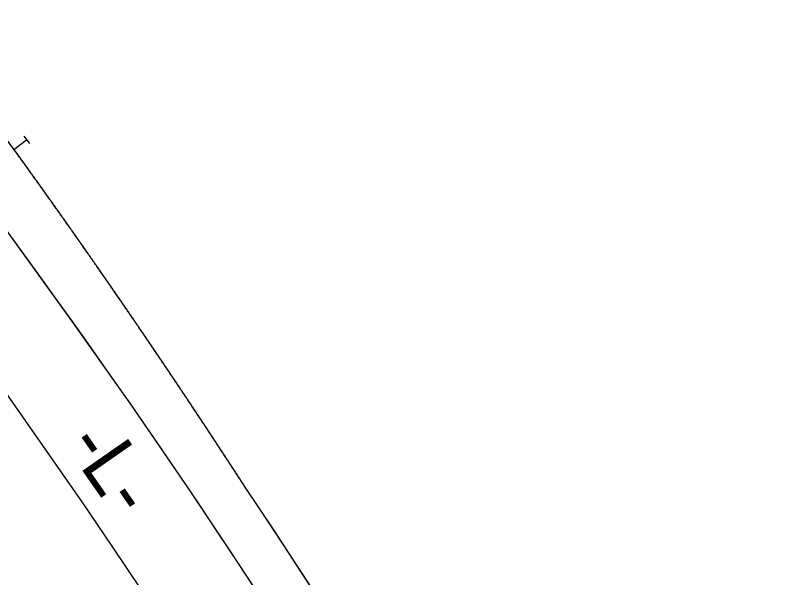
# Model space of a CAD drawing. Extents: x 2057680 to 2059216, y 687940 to 689338.
# Drawn here: x 2058908.2 to 2059006.1, y 688642.4 to 688713 of the extents above; entities that cross this region are included whole.
import ezdxf

# ---------------------------------------------------------------- set-up
doc = ezdxf.new("R2010")
doc.units = 0
for name, color, linetype in [('Cogo Default Point CELL', 7, 'Continuous'), ('COGO Default Point Elevation', 7, 'Continuous'), ('Exist DTM Breakline Cogo Number', 7, 'Continuous'), ('Exist DTM Breakline Cogo Point CELL', 7, 'Continuous'), ('Exist DTM Regular Point Underwater Cogo Number', 7, 'Continuous'), ('Exist Roads EOP Cogo Elevation', 7, 'Continuous'), ('Exist Structure Major Bridge WW Cogo Point CELL', 7, 'Continuous'), ('Exist Structure Major Deck Tunnel Box Culvert Cogo Elevation', 7, 'Continuous'), ('Exist Structure Major Deck Tunnel Box Culvert Cogo Number', 7, 'Continuous')]:
    doc.layers.add(name, color=color, linetype=linetype)

msp = doc.modelspace()

# ---------------------------------------------------------------- linework, layer by layer
at = {"layer": 'Cogo Default Point CELL'}
msp.add_arc((2058091.567, 688086.697), 1000, 13.858564, 62.505867, dxfattribs=at)
at = {"layer": 'Exist DTM Breakline Cogo Number'}
for p, q in [((2058907.962, 688696.191), (2058909.553, 688697.403)), ((2058909.206, 688697.859), (2058909.9, 688696.947))]:
    msp.add_line(p, q, dxfattribs=at)
at = {"layer": 'Exist DTM Breakline Cogo Point CELL'}
for radius, start, end in [(1018.818, 36.724192, 37.798292), (1018.01, 21.684059, 33.859403)]:
    msp.add_arc((2058091.567, 688086.697), radius, start, end, dxfattribs=at)
msp.add_spline([(2058936.93, 688653.889), (2058936.555, 688654.466), (2058936.181, 688655.043), (2058935.805, 688655.619), (2058935.43, 688656.196), (2058935.054, 688656.772), (2058934.678, 688657.348), (2058934.301, 688657.924), (2058933.924, 688658.499), (2058933.546, 688659.074), (2058933.168, 688659.649), (2058932.79, 688660.224), (2058932.411, 688660.798), (2058932.032, 688661.372), (2058931.653, 688661.946), (2058931.273, 688662.52), (2058930.893, 688663.093), (2058930.512, 688663.666), (2058930.131, 688664.239), (2058929.75, 688664.812), (2058929.368, 688665.384), (2058928.985, 688665.957), (2058928.603, 688666.529), (2058928.22, 688667.1), (2058927.837, 688667.672), (2058927.453, 688668.243), (2058927.069, 688668.814), (2058926.684, 688669.384), (2058926.299, 688669.955), (2058925.914, 688670.525), (2058925.528, 688671.095), (2058925.142, 688671.664), (2058924.755, 688672.234), (2058924.368, 688672.803), (2058923.981, 688673.372), (2058923.594, 688673.94), (2058923.205, 688674.509), (2058922.817, 688675.077), (2058922.428, 688675.645), (2058922.039, 688676.212), (2058921.649, 688676.779), (2058921.259, 688677.346), (2058920.869, 688677.913), (2058920.478, 688678.48), (2058920.087, 688679.046), (2058919.695, 688679.612), (2058919.304, 688680.178), (2058918.911, 688680.743), (2058918.519, 688681.309), (2058918.125, 688681.874), (2058917.732, 688682.438), (2058917.338, 688683.003), (2058916.944, 688683.567), (2058916.549, 688684.131), (2058916.154, 688684.695), (2058915.759, 688685.258), (2058915.363, 688685.821), (2058914.967, 688686.384), (2058914.57, 688686.947), (2058914.173, 688687.509), (2058913.776, 688688.071), (2058913.378, 688688.633), (2058912.98, 688689.195), (2058912.582, 688689.756), (2058912.183, 688690.317), (2058911.784, 688690.878), (2058911.384, 688691.439), (2058910.984, 688691.999), (2058910.584, 688692.559), (2058910.183, 688693.119), (2058909.782, 688693.678), (2058909.38, 688694.237), (2058908.978, 688694.796), (2058908.173, 688695.913)], degree=3, dxfattribs=at)
at = {"layer": 'Exist DTM Regular Point Underwater Cogo Number'}
msp.add_arc((2058091.567, 688086.697), 1018, 21.684059, 33.859412, dxfattribs=at)
msp.add_spline([(2058936.921, 688653.883), (2058936.547, 688654.46), (2058936.172, 688655.037), (2058935.797, 688655.614), (2058935.422, 688656.19), (2058935.046, 688656.766), (2058934.669, 688657.342), (2058934.293, 688657.918), (2058933.915, 688658.493), (2058933.538, 688659.069), (2058933.16, 688659.644), (2058932.782, 688660.218), (2058932.403, 688660.793), (2058932.024, 688661.367), (2058931.644, 688661.941), (2058931.265, 688662.514), (2058930.884, 688663.088), (2058930.504, 688663.661), (2058930.123, 688664.234), (2058929.741, 688664.806), (2058929.359, 688665.379), (2058928.977, 688665.951), (2058928.595, 688666.523), (2058928.212, 688667.095), (2058927.828, 688667.666), (2058927.444, 688668.237), (2058927.06, 688668.808), (2058926.676, 688669.379), (2058926.291, 688669.949), (2058925.905, 688670.519), (2058925.52, 688671.089), (2058925.134, 688671.659), (2058924.747, 688672.228), (2058924.36, 688672.797), (2058923.973, 688673.366), (2058923.585, 688673.935), (2058923.197, 688674.503), (2058922.809, 688675.071), (2058922.42, 688675.639), (2058922.031, 688676.206), (2058921.641, 688676.774), (2058921.251, 688677.341), (2058920.861, 688677.908), (2058920.47, 688678.474), (2058920.079, 688679.04), (2058919.687, 688679.606), (2058919.295, 688680.172), (2058918.903, 688680.738), (2058918.51, 688681.303), (2058918.117, 688681.868), (2058917.724, 688682.433), (2058917.33, 688682.997), (2058916.936, 688683.561), (2058916.541, 688684.125), (2058916.146, 688684.689), (2058915.751, 688685.252), (2058915.355, 688685.816), (2058914.959, 688686.379), (2058914.562, 688686.941), (2058914.165, 688687.504), (2058913.768, 688688.066), (2058913.37, 688688.628), (2058912.972, 688689.189), (2058912.574, 688689.75), (2058912.175, 688690.312), (2058911.775, 688690.872), (2058911.376, 688691.433), (2058910.976, 688691.993), (2058910.575, 688692.553), (2058910.175, 688693.113), (2058909.773, 688693.672), (2058909.372, 688694.232), (2058908.97, 688694.791), (2058908.165, 688695.908)], degree=3, dxfattribs=at)
at = {"layer": 'Exist Roads EOP Cogo Elevation'}
msp.add_spline([(2058869.627, 688683.82), (2058870.234, 688683.022), (2058870.781, 688682.301), (2058871.329, 688681.578), (2058871.875, 688680.856), (2058872.421, 688680.132), (2058872.966, 688679.409), (2058873.51, 688678.684), (2058874.054, 688677.96), (2058874.597, 688677.234), (2058875.14, 688676.509), (2058875.681, 688675.782), (2058876.222, 688675.056), (2058876.763, 688674.328), (2058877.302, 688673.601), (2058877.841, 688672.872), (2058878.38, 688672.144), (2058878.918, 688671.414), (2058879.455, 688670.685), (2058879.991, 688669.954), (2058880.527, 688669.224), (2058881.062, 688668.493), (2058881.596, 688667.761), (2058882.129, 688667.029), (2058882.662, 688666.296), (2058883.195, 688665.563), (2058883.726, 688664.829), (2058884.257, 688664.095), (2058884.787, 688663.36), (2058885.317, 688662.625), (2058885.846, 688661.89), (2058886.374, 688661.154), (2058886.902, 688660.417), (2058887.428, 688659.68), (2058887.954, 688658.942), (2058888.48, 688658.204), (2058889.005, 688657.466), (2058889.529, 688656.727), (2058890.052, 688655.987), (2058890.575, 688655.248), (2058891.097, 688654.507), (2058891.618, 688653.766), (2058892.139, 688653.025), (2058892.659, 688652.283), (2058893.178, 688651.541), (2058893.697, 688650.798), (2058894.215, 688650.055), (2058894.732, 688649.311), (2058895.248, 688648.566), (2058895.764, 688647.822), (2058896.279, 688647.077), (2058896.794, 688646.331), (2058897.308, 688645.585), (2058897.821, 688644.838), (2058898.333, 688644.091), (2058898.845, 688643.344), (2058899.356, 688642.596), (2058899.866, 688641.847), (2058900.376, 688641.098), (2058900.885, 688640.349), (2058901.393, 688639.599), (2058901.9, 688638.848), (2058902.407, 688638.098), (2058902.913, 688637.346), (2058903.419, 688636.595), (2058903.924, 688635.842), (2058904.428, 688635.09), (2058904.931, 688634.336), (2058905.434, 688633.583), (2058905.936, 688632.829), (2058906.437, 688632.074), (2058906.937, 688631.319), (2058907.437, 688630.564), (2058907.936, 688629.808), (2058908.435, 688629.052)], degree=3, dxfattribs=at)
at = {"layer": 'Exist Structure Major Bridge WW Cogo Point CELL'}
for radius, start, end in [(1018.808, 36.724201, 37.180075), (1018, 21.684059, 33.859412)]:
    msp.add_arc((2058091.567, 688086.697), radius, start, end, dxfattribs=at)
msp.add_spline([(2058936.921, 688653.883), (2058936.547, 688654.46), (2058936.172, 688655.037), (2058935.797, 688655.614), (2058935.422, 688656.19), (2058935.046, 688656.766), (2058934.669, 688657.342), (2058934.293, 688657.918), (2058933.915, 688658.493), (2058933.538, 688659.069), (2058933.16, 688659.644), (2058932.782, 688660.218), (2058932.403, 688660.793), (2058932.024, 688661.367), (2058931.644, 688661.941), (2058931.265, 688662.514), (2058930.884, 688663.088), (2058930.504, 688663.661), (2058930.123, 688664.234), (2058929.741, 688664.806), (2058929.359, 688665.379), (2058928.977, 688665.951), (2058928.595, 688666.523), (2058928.212, 688667.095), (2058927.828, 688667.666), (2058927.444, 688668.237), (2058927.06, 688668.808), (2058926.676, 688669.379), (2058926.291, 688669.949), (2058925.905, 688670.519), (2058925.52, 688671.089), (2058925.134, 688671.659), (2058924.747, 688672.228), (2058924.36, 688672.797), (2058923.973, 688673.366), (2058923.585, 688673.935), (2058923.197, 688674.503), (2058922.809, 688675.071), (2058922.42, 688675.639), (2058922.031, 688676.206), (2058921.641, 688676.774), (2058921.251, 688677.341), (2058920.861, 688677.908), (2058920.47, 688678.474), (2058920.079, 688679.04), (2058919.687, 688679.606), (2058919.295, 688680.172), (2058918.903, 688680.738), (2058918.51, 688681.303), (2058918.117, 688681.868), (2058917.724, 688682.433), (2058917.33, 688682.997), (2058916.936, 688683.561), (2058916.541, 688684.125), (2058916.146, 688684.689), (2058915.751, 688685.252), (2058915.355, 688685.816), (2058914.959, 688686.379), (2058914.562, 688686.941), (2058914.165, 688687.504), (2058913.768, 688688.066), (2058913.37, 688688.628), (2058912.972, 688689.189), (2058912.574, 688689.75), (2058912.175, 688690.312), (2058911.775, 688690.872), (2058911.376, 688691.433), (2058910.976, 688691.993), (2058910.575, 688692.553), (2058910.175, 688693.113), (2058909.773, 688693.672), (2058909.372, 688694.232), (2058908.97, 688694.791), (2058908.165, 688695.908)], degree=3, dxfattribs=at)
at = {"layer": 'Exist Structure Major Deck Tunnel Box Culvert Cogo Elevation'}
for radius, start, end in [(1018.808, 36.724201, 37.108698), (1012, 13.858564, 37.177324), (1018, 21.684059, 33.859412)]:
    msp.add_arc((2058091.567, 688086.697), radius, start, end, dxfattribs=at)
for points in [[(2058917.984, 688682.06), (2058917.897, 688682.184), (2058917.81, 688682.308), (2058917.724, 688682.433), (2058917.593, 688682.621), (2058917.461, 688682.809), (2058917.33, 688682.997), (2058917.199, 688683.185), (2058917.067, 688683.373), (2058916.936, 688683.561), (2058916.804, 688683.749), (2058916.673, 688683.937), (2058916.541, 688684.125), (2058916.409, 688684.313), (2058916.278, 688684.501), (2058916.146, 688684.689), (2058916.014, 688684.877), (2058915.882, 688685.065), (2058915.751, 688685.252), (2058915.619, 688685.44), (2058915.487, 688685.628), (2058915.355, 688685.816), (2058915.223, 688686.003), (2058915.091, 688686.191), (2058914.959, 688686.379), (2058914.826, 688686.566), (2058914.694, 688686.754), (2058914.562, 688686.941), (2058914.43, 688687.129), (2058914.297, 688687.316), (2058914.165, 688687.504), (2058914.033, 688687.691), (2058913.9, 688687.878), (2058913.768, 688688.066), (2058913.635, 688688.253), (2058913.503, 688688.44), (2058913.37, 688688.628), (2058913.237, 688688.815), (2058913.105, 688689.002), (2058912.972, 688689.189), (2058912.839, 688689.376), (2058912.706, 688689.563), (2058912.574, 688689.75), (2058912.441, 688689.938), (2058912.308, 688690.125), (2058912.175, 688690.312), (2058912.042, 688690.498), (2058911.909, 688690.685), (2058911.775, 688690.872), (2058911.642, 688691.059), (2058911.509, 688691.246), (2058911.376, 688691.433), (2058911.243, 688691.62), (2058911.109, 688691.806), (2058910.976, 688691.993), (2058910.842, 688692.18), (2058910.709, 688692.367), (2058910.575, 688692.553), (2058910.442, 688692.74), (2058910.308, 688692.926), (2058910.175, 688693.113), (2058910.041, 688693.299), (2058909.907, 688693.486), (2058909.773, 688693.672), (2058909.64, 688693.859), (2058909.506, 688694.045), (2058909.372, 688694.232), (2058909.238, 688694.418), (2058909.104, 688694.604), (2058908.97, 688694.791), (2058908.702, 688695.163), (2058908.433, 688695.535), (2058908.165, 688695.908)], [(2058927.57, 688668.051), (2058927.528, 688668.113), (2058927.486, 688668.175), (2058927.444, 688668.237), (2058927.316, 688668.427), (2058927.188, 688668.618), (2058927.06, 688668.808), (2058926.932, 688668.998), (2058926.804, 688669.189), (2058926.676, 688669.379), (2058926.547, 688669.569), (2058926.419, 688669.759), (2058926.291, 688669.949), (2058926.162, 688670.139), (2058926.034, 688670.329), (2058925.905, 688670.519), (2058925.777, 688670.709), (2058925.648, 688670.899), (2058925.52, 688671.089), (2058925.391, 688671.279), (2058925.262, 688671.469), (2058925.134, 688671.659), (2058925.005, 688671.849), (2058924.876, 688672.038), (2058924.747, 688672.228), (2058924.618, 688672.418), (2058924.489, 688672.608), (2058924.36, 688672.797), (2058924.231, 688672.987), (2058924.102, 688673.176), (2058923.973, 688673.366), (2058923.844, 688673.556), (2058923.715, 688673.745), (2058923.585, 688673.935), (2058923.456, 688674.124), (2058923.327, 688674.314), (2058923.197, 688674.503), (2058923.068, 688674.692), (2058922.938, 688674.882), (2058922.809, 688675.071), (2058922.679, 688675.26), (2058922.55, 688675.45), (2058922.42, 688675.639), (2058922.29, 688675.828), (2058922.161, 688676.017), (2058922.031, 688676.206), (2058921.901, 688676.396), (2058921.771, 688676.585), (2058921.641, 688676.774), (2058921.511, 688676.963), (2058921.381, 688677.152), (2058921.251, 688677.341), (2058921.121, 688677.53), (2058920.991, 688677.719), (2058920.861, 688677.908), (2058920.731, 688678.097), (2058920.6, 688678.285), (2058920.47, 688678.474), (2058920.34, 688678.663), (2058920.209, 688678.852), (2058920.079, 688679.04), (2058919.948, 688679.229), (2058919.818, 688679.418), (2058919.687, 688679.606), (2058919.557, 688679.795), (2058919.426, 688679.984), (2058919.295, 688680.172), (2058919.165, 688680.361), (2058919.034, 688680.549), (2058918.903, 688680.738), (2058918.772, 688680.926), (2058918.641, 688681.115), (2058918.51, 688681.303), (2058918.379, 688681.491), (2058918.248, 688681.68), (2058918.117, 688681.868), (2058918.073, 688681.932), (2058918.028, 688681.996), (2058917.984, 688682.06)], [(2058936.921, 688653.883), (2058936.797, 688654.076), (2058936.672, 688654.268), (2058936.547, 688654.46), (2058936.422, 688654.653), (2058936.297, 688654.845), (2058936.172, 688655.037), (2058936.047, 688655.23), (2058935.922, 688655.422), (2058935.797, 688655.614), (2058935.672, 688655.806), (2058935.547, 688655.998), (2058935.422, 688656.19), (2058935.296, 688656.382), (2058935.171, 688656.574), (2058935.046, 688656.766), (2058934.92, 688656.958), (2058934.795, 688657.15), (2058934.669, 688657.342), (2058934.544, 688657.534), (2058934.418, 688657.726), (2058934.293, 688657.918), (2058934.167, 688658.11), (2058934.041, 688658.302), (2058933.915, 688658.493), (2058933.79, 688658.685), (2058933.664, 688658.877), (2058933.538, 688659.069), (2058933.412, 688659.26), (2058933.286, 688659.452), (2058933.16, 688659.644), (2058933.034, 688659.835), (2058932.908, 688660.027), (2058932.782, 688660.218), (2058932.656, 688660.41), (2058932.529, 688660.601), (2058932.403, 688660.793), (2058932.277, 688660.984), (2058932.15, 688661.175), (2058932.024, 688661.367), (2058931.898, 688661.558), (2058931.771, 688661.749), (2058931.644, 688661.941), (2058931.518, 688662.132), (2058931.391, 688662.323), (2058931.265, 688662.514), (2058931.138, 688662.706), (2058931.011, 688662.897), (2058930.884, 688663.088), (2058930.758, 688663.279), (2058930.631, 688663.47), (2058930.504, 688663.661), (2058930.377, 688663.852), (2058930.25, 688664.043), (2058930.123, 688664.234), (2058929.996, 688664.425), (2058929.868, 688664.616), (2058929.741, 688664.806), (2058929.614, 688664.997), (2058929.487, 688665.188), (2058929.359, 688665.379), (2058929.232, 688665.57), (2058929.105, 688665.76), (2058928.977, 688665.951), (2058928.85, 688666.142), (2058928.722, 688666.332), (2058928.595, 688666.523), (2058928.467, 688666.714), (2058928.339, 688666.904), (2058928.212, 688667.095), (2058928.084, 688667.285), (2058927.956, 688667.476), (2058927.828, 688667.666), (2058927.742, 688667.794), (2058927.656, 688667.922), (2058927.57, 688668.051)]]:
    msp.add_open_spline(points, degree=3, dxfattribs=at)
at = {"layer": 'Exist Structure Major Deck Tunnel Box Culvert Cogo Number'}
for radius in [1012, 986]:
    msp.add_arc((2058091.567, 688086.697), radius, 13.858564, 62.505867, dxfattribs=at)

# ---------------------------------------------------------------- texts
at = {"layer": 'COGO Default Point Elevation'}
msp.add_text('-L-', height=7, rotation=304.89569, dxfattribs=at).set_placement((2058914.334, 688659.004))

doc.saveas('drawing.dxf')
